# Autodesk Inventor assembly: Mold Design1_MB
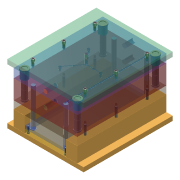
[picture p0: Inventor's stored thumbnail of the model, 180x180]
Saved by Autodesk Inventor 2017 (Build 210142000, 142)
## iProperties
Created: 2016-07
Part Number: Mold Design1_MB
Document SubType Name: Assembly
Designer: Sandeep
Author: Sandeep
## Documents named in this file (16)
- C:\Inventor_2017\c19\MB\FUTABA_SA-S 3\Mold Design1_MB.iam
- C:\Users\Sandeep\Documents\Inventor\Content Center Files\R2017\en-US\JIS 1176\JIS 1176 M12x40.ipt
- C:\Users\Sandeep\Documents\Inventor\Content Center Files\R2017\en-US\GBA\M-GBA 40x69.ipt
- C:\Inventor_2017\c19\MB\FUTABA_SA-S 3\Mold Design1_MB_SA-SB1.ipt
- C:\Inventor_2017\c19\MB\FUTABA_SA-S 3\Mold Design1_MB_SA-SB2.ipt
- C:\Inventor_2017\c19\MB\FUTABA_SA-S 3\Mold Design1_MB_SA-EP.ipt
- C:\Users\Sandeep\Documents\Inventor\Content Center Files\R2017\en-US\GPA\M-GPA40x217x69.ipt
- C:\Inventor_2017\c19\MB\FUTABA_SA-S 3\Mold Design1_MB_SA-ERP.ipt
- C:\Inventor_2017\c19\MB\FUTABA_SA-S 3\Mold Design1_MB_SA-BCP.ipt
- C:\Users\Sandeep\Documents\Inventor\Content Center Files\R2017\en-US\JIS 1176\JIS 1176 M16x35.ipt
- C:\Inventor_2017\c19\MB\FUTABA_SA-S 3\Mold Design1_MB_RPN.ipt
- C:\Inventor_2017\c19\MB\FUTABA_SA-S 3\Mold Design1_MB_SA-S-AP.ipt
- C:\Inventor_2017\c19\MB\FUTABA_SA-S 3\Mold Design1_MB_SA-S-BP.ipt
- C:\Inventor_2017\c19\MB\FUTABA_SA-S 3\Mold Design1_MB_SA-TCP.ipt
- C:\Inventor_2017\c19\MB\FUTABA_SA-S 3\Mold Design1_MB_SA-SP.ipt
- C:\Users\Sandeep\Documents\Inventor\Content Center Files\R2017\en-US\JIS 1176\JIS 1176 M16x210.ipt
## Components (37 placed, 15 different names)
1. Mold Design1_MB_SA-SB1:1 — Flush:1, Flush:3, Mate:1, Mate:5
2. Mold Design1_MB_SA-SB2:2 — Flush:2, Flush:4, Mate:2, Mate:6
3. Mold Design1_MB_SA-EP:1 — Insert:1, Flush:5, Flush:6, Ejection, Mate:4
4. Mold Design1_MB_SA-ERP:1 — Insert:7, Flush:7, Flush:8, Mate:4
5. Mold Design1_MB_SA-BCP:1 — Insert:8, Ejection, Flush:9, Flush:10, Mate:5, Mate:6
6. Mold Design1_MB_SA-S-AP:1 — Insert:2, Insert:5, Flush:11, Flush:12, Mate:7, PL1, Flush:19
7. Mold Design1_MB_SA-S-BP:1 — Insert:3, Insert:4, Flush:13, Flush:14, PL1, Mate:9
8. Mold Design1_MB_SA-TCP:1 — Insert:6, Mate:7, Flush:15, Flush:16
9. Mold Design1_MB_SA-SP:1 — Mate:1, Mate:2, Flush:17, Flush:18, Mate:9
10. GPA 40x217x69:1 — Insert:3
11. GPA 40x217x69:3
12. JIS 1176 M16x35:1 — Insert:6
13. JIS 1176 M16x35:2
14. JIS 1176 M16x35:3
15. JIS 1176 M16x35:4
16. JIS 1176 M16x35:5
17. JIS 1176 M16x35:6
18. JIS 1176 M12x40:1 — Insert:1
19. JIS 1176 M12x40:2
20. JIS 1176 M12x40:3
21. JIS 1176 M12x40:4
22. JIS 1176 M16x210:1 — Insert:8
23. JIS 1176 M16x210:2
24. JIS 1176 M16x210:3
25. JIS 1176 M16x210:4
26. JIS 1176 M16x210:5
27. JIS 1176 M16x210:6
28. GBA 40x69:1 — Insert:2
29. GBA 40x69:3
30. GPA 40x217x69:2 — Insert:4
31. GPA 40x217x69:4
32. Mold Design1_MB_RPN:1 — Insert:7
33. Mold Design1_MB_RPN:2
34. Mold Design1_MB_RPN:3
35. Mold Design1_MB_RPN:4
36. GBA 40x69:2 — Insert:5
37. GBA 40x69:4
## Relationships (36: Flush 19, Mate 9, Insert 8)
- Insert:1: Mold Design1_MB_SA-EP:1 ↔ JIS 1176 M12x40:1
- Insert:2: Mold Design1_MB_SA-S-AP:1 ↔ GBA 40x69:1
- Insert:3: Mold Design1_MB_SA-S-BP:1 ↔ GPA 40x217x69:1
- Insert:4: Mold Design1_MB_SA-S-BP:1 ↔ GPA 40x217x69:2
- Insert:5: Mold Design1_MB_SA-S-AP:1 ↔ GBA 40x69:2
- Insert:6: Mold Design1_MB_SA-TCP:1 ↔ JIS 1176 M16x35:1
- Insert:7: Mold Design1_MB_SA-ERP:1 ↔ Mold Design1_MB_RPN:1
- Insert:8: Mold Design1_MB_SA-BCP:1 ↔ JIS 1176 M16x210:1
- Flush:1: Mold Design1_MB_SA-SB1:1
- Flush:2: Mold Design1_MB_SA-SB2:2
- Flush:3: Mold Design1_MB_SA-SB1:1
- Flush:4: Mold Design1_MB_SA-SB2:2
- Mate:1: Mold Design1_MB_SA-SB1:1 ↔ Mold Design1_MB_SA-SP:1
- Mate:2: Mold Design1_MB_SA-SB2:2 ↔ Mold Design1_MB_SA-SP:1
- Flush:5: Mold Design1_MB_SA-EP:1
- Flush:6: Mold Design1_MB_SA-EP:1
- Ejection [Mate]: Mold Design1_MB_SA-EP:1 ↔ Mold Design1_MB_SA-BCP:1
- Flush:7: Mold Design1_MB_SA-ERP:1
- Flush:8: Mold Design1_MB_SA-ERP:1
- Mate:4: Mold Design1_MB_SA-EP:1 ↔ Mold Design1_MB_SA-ERP:1
- Flush:9: Mold Design1_MB_SA-BCP:1
- Flush:10: Mold Design1_MB_SA-BCP:1
- Mate:5: Mold Design1_MB_SA-SB1:1 ↔ Mold Design1_MB_SA-BCP:1
- Mate:6: Mold Design1_MB_SA-SB2:2 ↔ Mold Design1_MB_SA-BCP:1
- Flush:11: Mold Design1_MB_SA-S-AP:1
- Flush:12: Mold Design1_MB_SA-S-AP:1
- Mate:7: Mold Design1_MB_SA-S-AP:1 ↔ Mold Design1_MB_SA-TCP:1
- Flush:13: Mold Design1_MB_SA-S-BP:1
- Flush:14: Mold Design1_MB_SA-S-BP:1
- PL1 [Mate]: Mold Design1_MB_SA-S-AP:1 ↔ Mold Design1_MB_SA-S-BP:1
- Flush:15: Mold Design1_MB_SA-TCP:1
- Flush:16: Mold Design1_MB_SA-TCP:1
- Flush:17: Mold Design1_MB_SA-SP:1
- Flush:18: Mold Design1_MB_SA-SP:1
- Mate:9: Mold Design1_MB_SA-S-BP:1 ↔ Mold Design1_MB_SA-SP:1
- Flush:19: Mold Design1_MB_SA-S-AP:1
